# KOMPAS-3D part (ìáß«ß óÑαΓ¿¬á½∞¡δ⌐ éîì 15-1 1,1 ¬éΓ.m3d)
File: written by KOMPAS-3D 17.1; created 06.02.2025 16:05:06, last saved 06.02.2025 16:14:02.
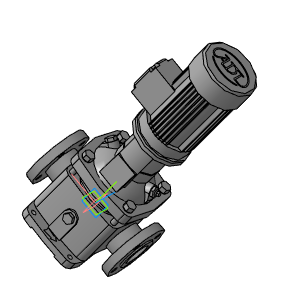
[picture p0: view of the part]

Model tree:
1. Операция без истории:1  (labels: Насос вертикальный ВМН 15-1 1,1 кВт)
